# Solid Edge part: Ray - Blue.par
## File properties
Author: hhakima
Template: Normal.par
Last saved by: hhakima
Revision: 10
Application: Solid Edge
Accuracy: 0.990
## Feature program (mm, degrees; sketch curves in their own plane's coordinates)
sketch for "unnamed Protrusion 1" plane through (0, 0, 0) normal (0, -1, 0) x-axis (1, 0, 0)
  circle centre (0, 0) radius 1.2
extrude "unnamed Protrusion 1" add finite 10.6 along -normal
sketch for "ExtrudedProtrusion_2" plane through (0, 0, 1.2) normal (1, 0, 0) x-axis (0, 1, 0)
extrude "ExtrudedProtrusion_2" add finite 93 along +normal
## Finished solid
Body 1: solid body, 7 faces, 10 edges, 5 vertices.
  Faces by surface: plane 5, cylinder 2
  Edges by curve: circle 5, intersection 3, line 2
Bounding box of the edges (mm): 94.200 x 10.600 x 2.500, from (-1.2, 0, -1.25) to (93, 10.6, 1.25).
Cylindrical faces by radius (mm): R1.2 x1, R1.25 x1
Planar faces by outward normal: +x 1, +y 1, -x 2, -y 1
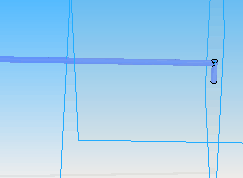
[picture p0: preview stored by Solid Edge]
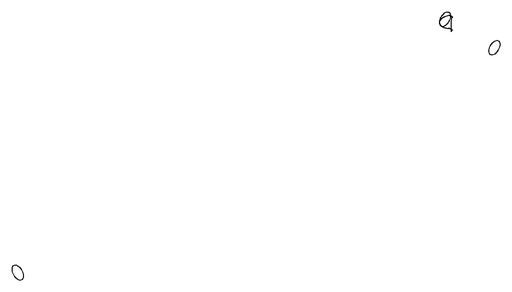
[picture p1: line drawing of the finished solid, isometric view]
